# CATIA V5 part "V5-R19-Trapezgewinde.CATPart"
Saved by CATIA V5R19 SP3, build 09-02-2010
Part number: Part1
Bounding box of the stored display mesh (mm): x -51 to 51, y -50.998 to 51, z 0 to 150
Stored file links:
  \\s050023f.de050.corpintra.net\tharmen$\data\my documents\V5-R19-Trapezgewinde.CATPart
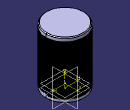
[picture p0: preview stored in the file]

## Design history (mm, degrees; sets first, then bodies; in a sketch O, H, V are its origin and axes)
Set1
  Plane1: type Offset, RefPlane xy-plane, Offset 10
  Helix1: Direction Sketch3, RefPoint Sketch4, Pitch 3, Height 130, TaperAngle 0
Body1 (main body)
  Sketch1 on xy-plane, origin (0, 0, 0), H (1, 0, 0), V (0, 1, 0)
    circle A1 centre (0, 0) radius 50
    radius A1 = 50
  Pad1: profile Sketch1, direction (0, 0, 1), length 150
  Chamfer1: length 2, angle 45, on face of Pad1 from Sketch1.A1
  Sketch2 on zx-plane, origin (0, 0, 0), H (-1, 0, 0), V (0, 0, 1)
    line L1 (-50, 9) -> (-50, 11)
    point P2 (-50, 11)
    line L2 (-50, 11) -> (-51, 10.5)
    point P3 (-51, 10.5)
    line L3 (-51, 10.5) -> (-51, 9.5)
    line L4 (-51, 9.5) -> (-50, 9)
    reference projected point E1 (-50, 10) from Sketch4
    reference projected point E2 (-50, 10) from Sketch4
    length L1 = 2
    length L3 = 1
    distance P3 P2 V = 0.5
    distance L3 L1 = 1
    distance P2 E2 = 1
    vertical: L1 V, L3 V
    coincidence: L1 E1
  Sketch3 on zx-plane, origin (0, 0, 0), H (-1, 0, 0), V (0, 0, 1)
    line L1 (0, 10.3484) -> (0, 17.4313)
    point P1 (0, 10.3484)
    coincidence: P1 V
    vertical: L1 V
  Sketch4 on Plane1, origin (0, 0, 10), H (1, 0, 0), V (0, 1, 0)
    point P1 (50, 0)
    distance P1 V = 50
    coincidence: P1 H
  Rib1: profile Sketch2, centre curve Helix1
